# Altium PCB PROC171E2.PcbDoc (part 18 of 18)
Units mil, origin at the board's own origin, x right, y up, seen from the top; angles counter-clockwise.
Board outline 7700 x 2300 mil, 6 copper layers (Top Layer, GND 1, SIG 1, SIG 2, GND 2, Bottom Layer), stack 61.062 mil thick; 937 components, 687 nets, 11931 pads, 1719 vias.
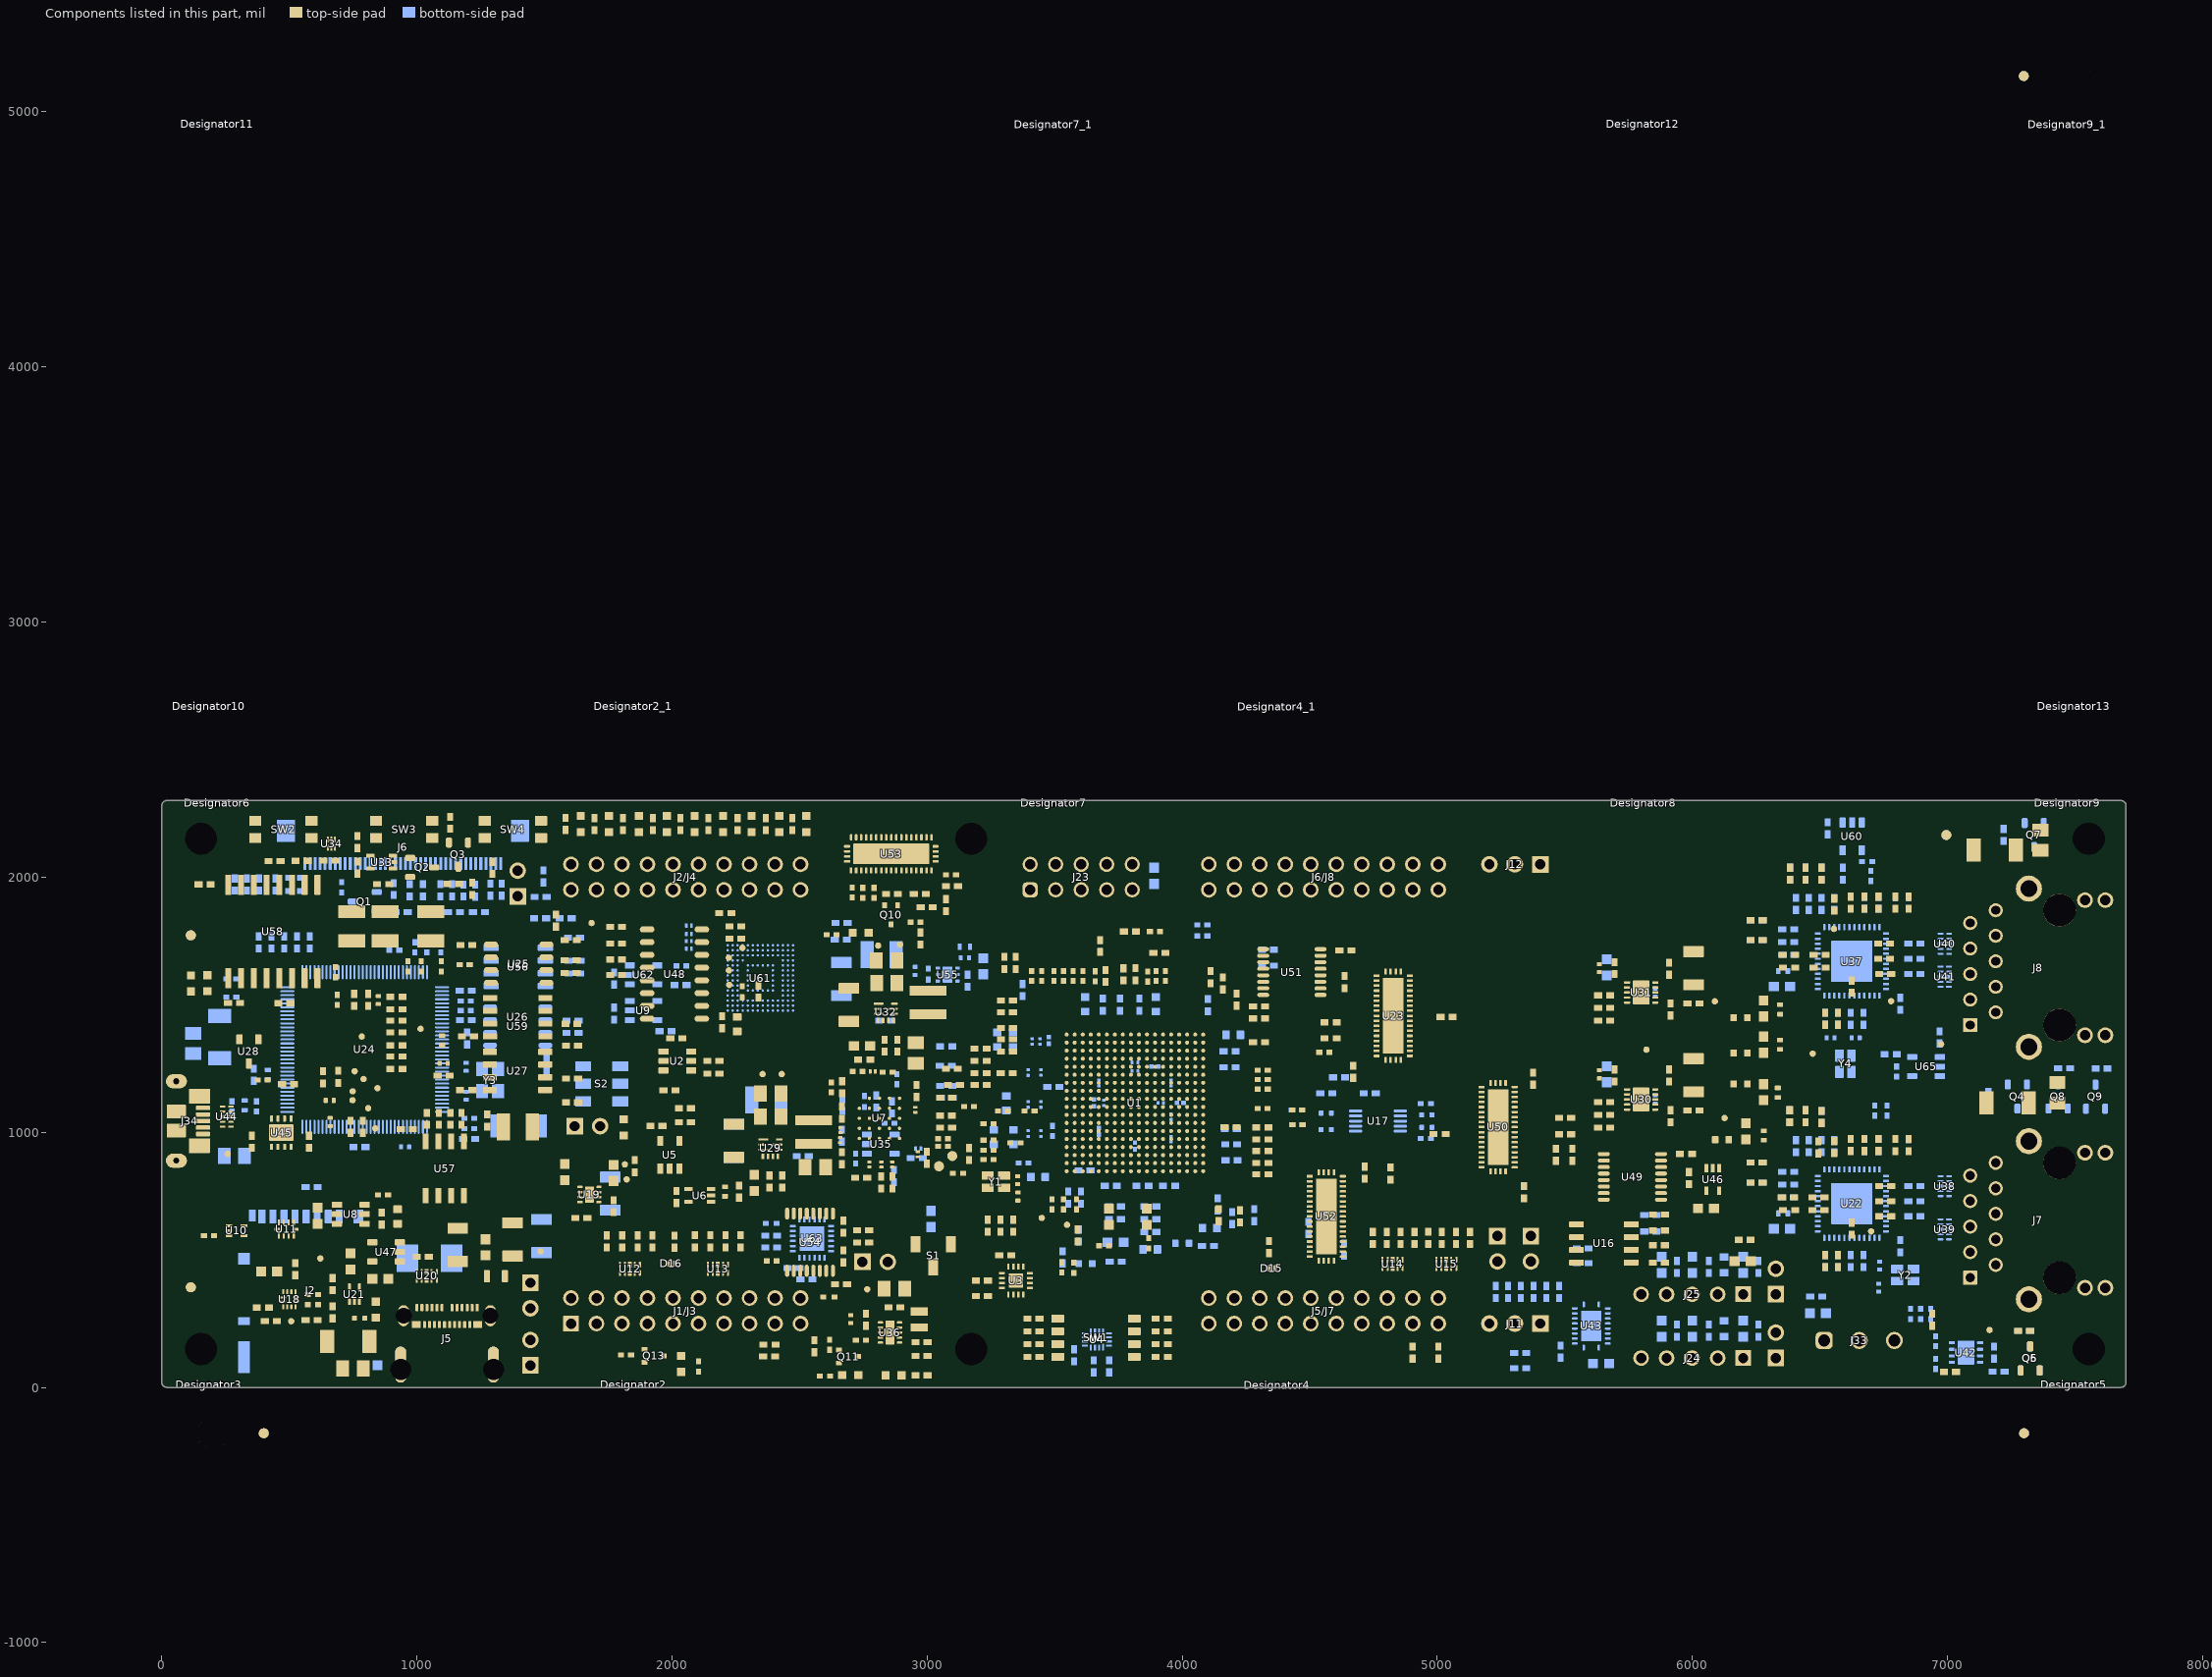
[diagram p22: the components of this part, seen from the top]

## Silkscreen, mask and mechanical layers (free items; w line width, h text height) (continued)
LP Logo:
  drawing of 8965 lines, arcs and shapes, not listed
  text "4" at 6539.42,724 h30
  text "6" at 6676.42,724 h30
  text "4" at 6198.42,635 h30
  text "6" at 6068.42,634 h30
  text "6" at 6255.42,633 h30
  text "4" at 6010.42,631 h30
  text "6" at 412.42,629 h30
  text "4" at 360.42,626 h30
  text "2" at 985.42,595 h30
  text "20" at 1896.42,592 h30
  text "3" at 6581.42,592 h30
  text "20" at 4395.42,588 h30
  text "2" at 3492.42,587 h30
  text "6" at 6660.42,573 h30
  text "4" at 6555.42,571 h30
  text "6" at -206.58,550 h30
  text "J2" at 2005.42,504 h30
  text "J6" at 4503.42,503 h30
  text "4" at -207.58,490 h30
  text "3" at 6199.42,490 h30
  text "3" at 6007.42,488 h30
  text "3" at -54.58,482 h30
  text "3" at 356.42,461 h30
  text "3" at 6579.42,436 h30
  text "5" at 79.42,424 h30
  text "4" at 6005.42,421 h30
  text "4" at 429.42,419 h30
  text "3" at 5867.42,419 h30
  text "B" at -273.58,401 h30
  text "J4" at 2002.42,392 h30
  text "J8" at 4500.42,391 h30
  text "6" at 6003.42,369 h30
  text "5" at 489.51,350.88 h30
  text "40" at -334.58,347 h30
  text "6" at 167.92,345 h30
  text "NOT FCC APPROVED FOR RESALE" at 6690.44,345.25 h50 r90
  text "20" at -110.58,339 h30 r270
  text "16" at 276.42,336 h30 r270
  text "19" at 1905.42,315 h30
  text "19" at 4398.42,312 h30
  text "8" at 489.51,290.88 h30
  text "FOR EVALUATION ONLY;" at 6590.49,290.27 h50 r90
  text "5" at 770.42,273 h30
  text "13" at 275.42,270 h30 r270
  text "16" at -71.58,262 h30
  text "A" at 1207.42,260 h30
  text "10" at 180.42,259 h30
  text "B" at 1512.42,240 h30
  text "13" at 4353.42,240 h30
  text "10" at 3277.42,239 h30
  text "12" at 4019.42,238 h30
  text "12" at 353.42,224 h30
  text "9" at 428.42,217 h30
  text "3" at 2476.42,213 h30
  text "5" at 4356.42,192 h30
  text "15" at -6.58,178 h30
  text "11" at 102.42,177 h30
  text "3" at 926.42,159 h30
  text "4" at 737.42,158 h30
  text "3" at 4510.42,149 h30
  text "4" at 4359.92,146 h30
  text "5" at 3491.09,124.33 h30
  text "5" at 2323.42,109 h30
  text "6" at 3270.42,92 h30
  text "4" at 2473.42,78 h30
  text "A" at 260.42,38 h30
  text "97" at 207.42,-61 h30
  text "128" at 716.42,-61 h30
  text "24" at 4328.42,-81 h30
  text "6" at 4329.42,-151 h30
  text "5" at 4154.42,-155 h30
  text "16" at 5343.42,-157 h30
  text "5" at 4905.42,-191 h30
  text "4" at 4832.42,-193 h30
  text "3" at 5775.42,-206 h30
  text "4" at 5904.42,-216 h30
  text "WHEN ACTUATOR IS OPENED" at -616.5,-219 h30 r270
  text "4" at -222.58,-222 h30
  text "6" at 5904.42,-266 h30
  text "3" at 967.42,-273 h30
  text "4" at 1055.42,-276 h30
  text "3" at 5774.42,-316 h30
  text "4" at 5900.42,-328 h30
  text "TEST AUTOMATION" at -357.58,-338 h30 r270
  text "3" at -229.58,-344 h30
  text "3" at 4833.42,-382 h30
  text "6" at 5899.42,-386 h30
  text "5" at 1055.42,-398 h30
  text "2" at -100.58,-404 h30
  text "39" at 3575.42,-458 h30 r270
  text "42" at 3640.42,-458 h30 r270
  text "4" at 5907.42,-458 h30
  text "C" at 2396.42,-459 h30
  text "3" at 5765.42,-462 h30
  text "9" at 5333.09,-500.67 h30
  text "6" at 5904.42,-509 h30
  text "38" at 3524.42,-510 h30
  text "6" at -160.58,-512 h30
  text "8" at 5594.42,-543 h30
  text "6" at 4327.42,-579 h30
  text "5" at 4150.42,-580 h30
  text "3" at 5607.42,-588 h30
  text "4" at 5741.42,-589 h30
  text "4" at -174.58,-605 h30
  text "3" at -409.58,-627 h30
  text "6" at 5741.42,-643 h30
  text "4" at -250.58,-664 h30
  text "65" at 93.42,-668 h30
  text "32" at 816.42,-672 h30
  text "3" at 5608.42,-703 h30
  text "4" at 5742.42,-705 h30
  text "5" at -252.58,-744 h30
  text "6" at 5740.42,-756 h30
  text "64" at 206.42,-782 h30
  text "33" at 699.42,-786 h30
  text "4" at 75.42,-792 h30
  text "22" at 3529.42,-824 h30
  text "C" at 1211.42,-886 h30
  text "www.ti.com/launchpad" at 3329.42,-889 h30 r90
  text "21" at 3576.42,-902 h30 r270
  text "18" at 3643.42,-907 h30 r270
  text "3" at 25.42,-908 h30
  text "2" at 151.42,-911 h30
  text "5" at 4928.42,-953 h30
  text "8" at 1973.42,-962 h30
  text "4" at 4851.42,-962 h30
  text "16" at 827.42,-974 h30
  text "9" at 628.42,-977 h30
  text "4" at 5923.42,-994 h30
  text "5" at 1964.42,-1067 h30
  text "4" at 2072.42,-1083 h30
  text "2" at 980.42,-1104 h30
  text "20" at 4412.42,-1106 h30
  text "2" at 3482.42,-1107 h30
  text "20" at 1893.42,-1108 h30
  text "8" at 5775.42,-1126 h30
  text "Development Kit" at 3049.42,-1136 h30 r90
  text "LP-AM243" at 2998.42,-1138 h30 r90
  text "3" at 4851.42,-1156 h30
  text "5" at 5885.42,-1174 h30 r270
  text "J7" at 4501.42,-1192 h30
  text "J3" at 1997.42,-1194 h30
  text "7" at 4904.42,-1239 h30
  text "10" at 5140.42,-1241 h30
  text "J5" at 4498.42,-1304 h30
  text "J1" at 1994.42,-1306 h30
  text "8" at 623.42,-1315 h30
  text "2" at 4913.42,-1335 h30
  text "19" at 1872.42,-1387 h30
  text "19" at 4404.42,-1388 h30
  text "4" at 1864.42,-1476 h30
  text "3" at 2031.42,-1476 h30
DXF_MCU080A_PCB:
  drawing of 5130 lines, arcs and shapes, not listed
  text "R8" at 5451.17,2418.99 h24 r90
  text "R9" at 5375.19,2275.66 h24 r180
  text "J2" at 3148.95,2164.13 h40 r270
  text "D10" at 5462.52,2153.11 h25
  text "J4" at 4494.17,2020 h40 r180
  text "J1" at 3604.17,2000 h19.68
  text "C22" at 4253.22,1829.76 h30 r180
  text "C5" at 3429.76,1769.98 h30 r90
  text "C4" at 3494.76,1769.98 h30 r90
  text "R24" at 5446.17,1743.99 h24 r90
  text "C15" at 4839.54,1613 h24
  text "R25" at 5375.19,1597 h24 r180
  text "D13" at 5345.71,1451.89 h25 r180
  text "C16" at 4838.16,1363 h24
  text "C20" at 3259.76,1290 h40 r270
  text "R20" at 4345.19,1102 h24 r180
  text "R21" at 4531.78,1088 h24
  text "LBL1" at 4990.94,1075 h40 r270
  text "R22" at 4581.17,1073.99 h24 r90
  text "R33" at 5451.17,1067.85 h24 r90
  text "C18" at 4858.16,1023 h24
  text "R31" at 4722.18,1002.39 h24 r270
  text "R34" at 5370.19,926.02 h24 r180
  text "R40" at 4712.18,811.01 h24 r270
  text "C8" at 3309.65,793.06 h35 r270
  text "C17" at 4858.16,793.35 h24
  text "C6" at 3388,787.08 h30 r270
  text "C7" at 3452.49,787.08 h30 r270
  text "D16" at 5350.94,741.89 h25 r180
  text "R49" at 4712.18,576.01 h24 r270
  text "C19" at 4858.16,563.23 h24
  text "C23" at 4249.14,502.76 h30 r180
  text "R51" at 4011.17,486.4 h35 r90
  text "R42" at 5449.79,392.1 h24 r90
  text "J3" at 4494.17,320 h40 r180
  text "R43" at 5375.19,250.27 h24 r180
  text "D15" at 5248.44,233.38 h25 r135
  text "R1" at 3215.19,202 h24 r180
  text "D17" at 5314.94,103.97 h25 r135

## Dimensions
7683.98,2300 to 7683.98,0 on M2 Board Dimensions
7683.98,4960 to 7683.98,2660 on M2 Board Dimensions
-1,5240 to 7699,5240 on M2 Board Dimensions
7699,5240 to 7700,-280 on M2 Board Dimensions
0,2280 to 20,2300 on M2 Board Dimensions
0,-400 to 1000,-400 on M2 Board Dimensions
